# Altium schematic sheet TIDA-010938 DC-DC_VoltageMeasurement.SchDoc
size 431 x 279 mm; Date: Not shown in title block; ApprovedBy: Not shown in title block; CheckedBy: Not shown in title block; Author: Not shown in title block; CompanyName: Not shown in title block; Engineer: Not shown in title block; Organization: Not shown in title block; Address1: Not shown in title block; Address2: Not shown in title block; Address3: Not shown in title block; Address4: Not shown in title block; DocumentNumber: 1; Revision: Use project parameter SCH_Rev; SheetNumber: 8; SheetTotal: 9; PageSetup: Record=PageOptions¦CenterHorizontal=True¦CenterVertical=True¦PrintScale=1.00¦XCorrection=1.00¦YCorrection=1.00¦PrintKind=0¦BorderSize=5000000¦LeftOffset=0¦BottomOffset=0¦Orientation=2¦PaperLength=1000¦PaperWidth=1000¦Scale=100¦PaperSource=15¦PrintQuality=600¦MediaType=1¦DitherType=10¦PaperKind=Letter¦PrintScaleMode=1
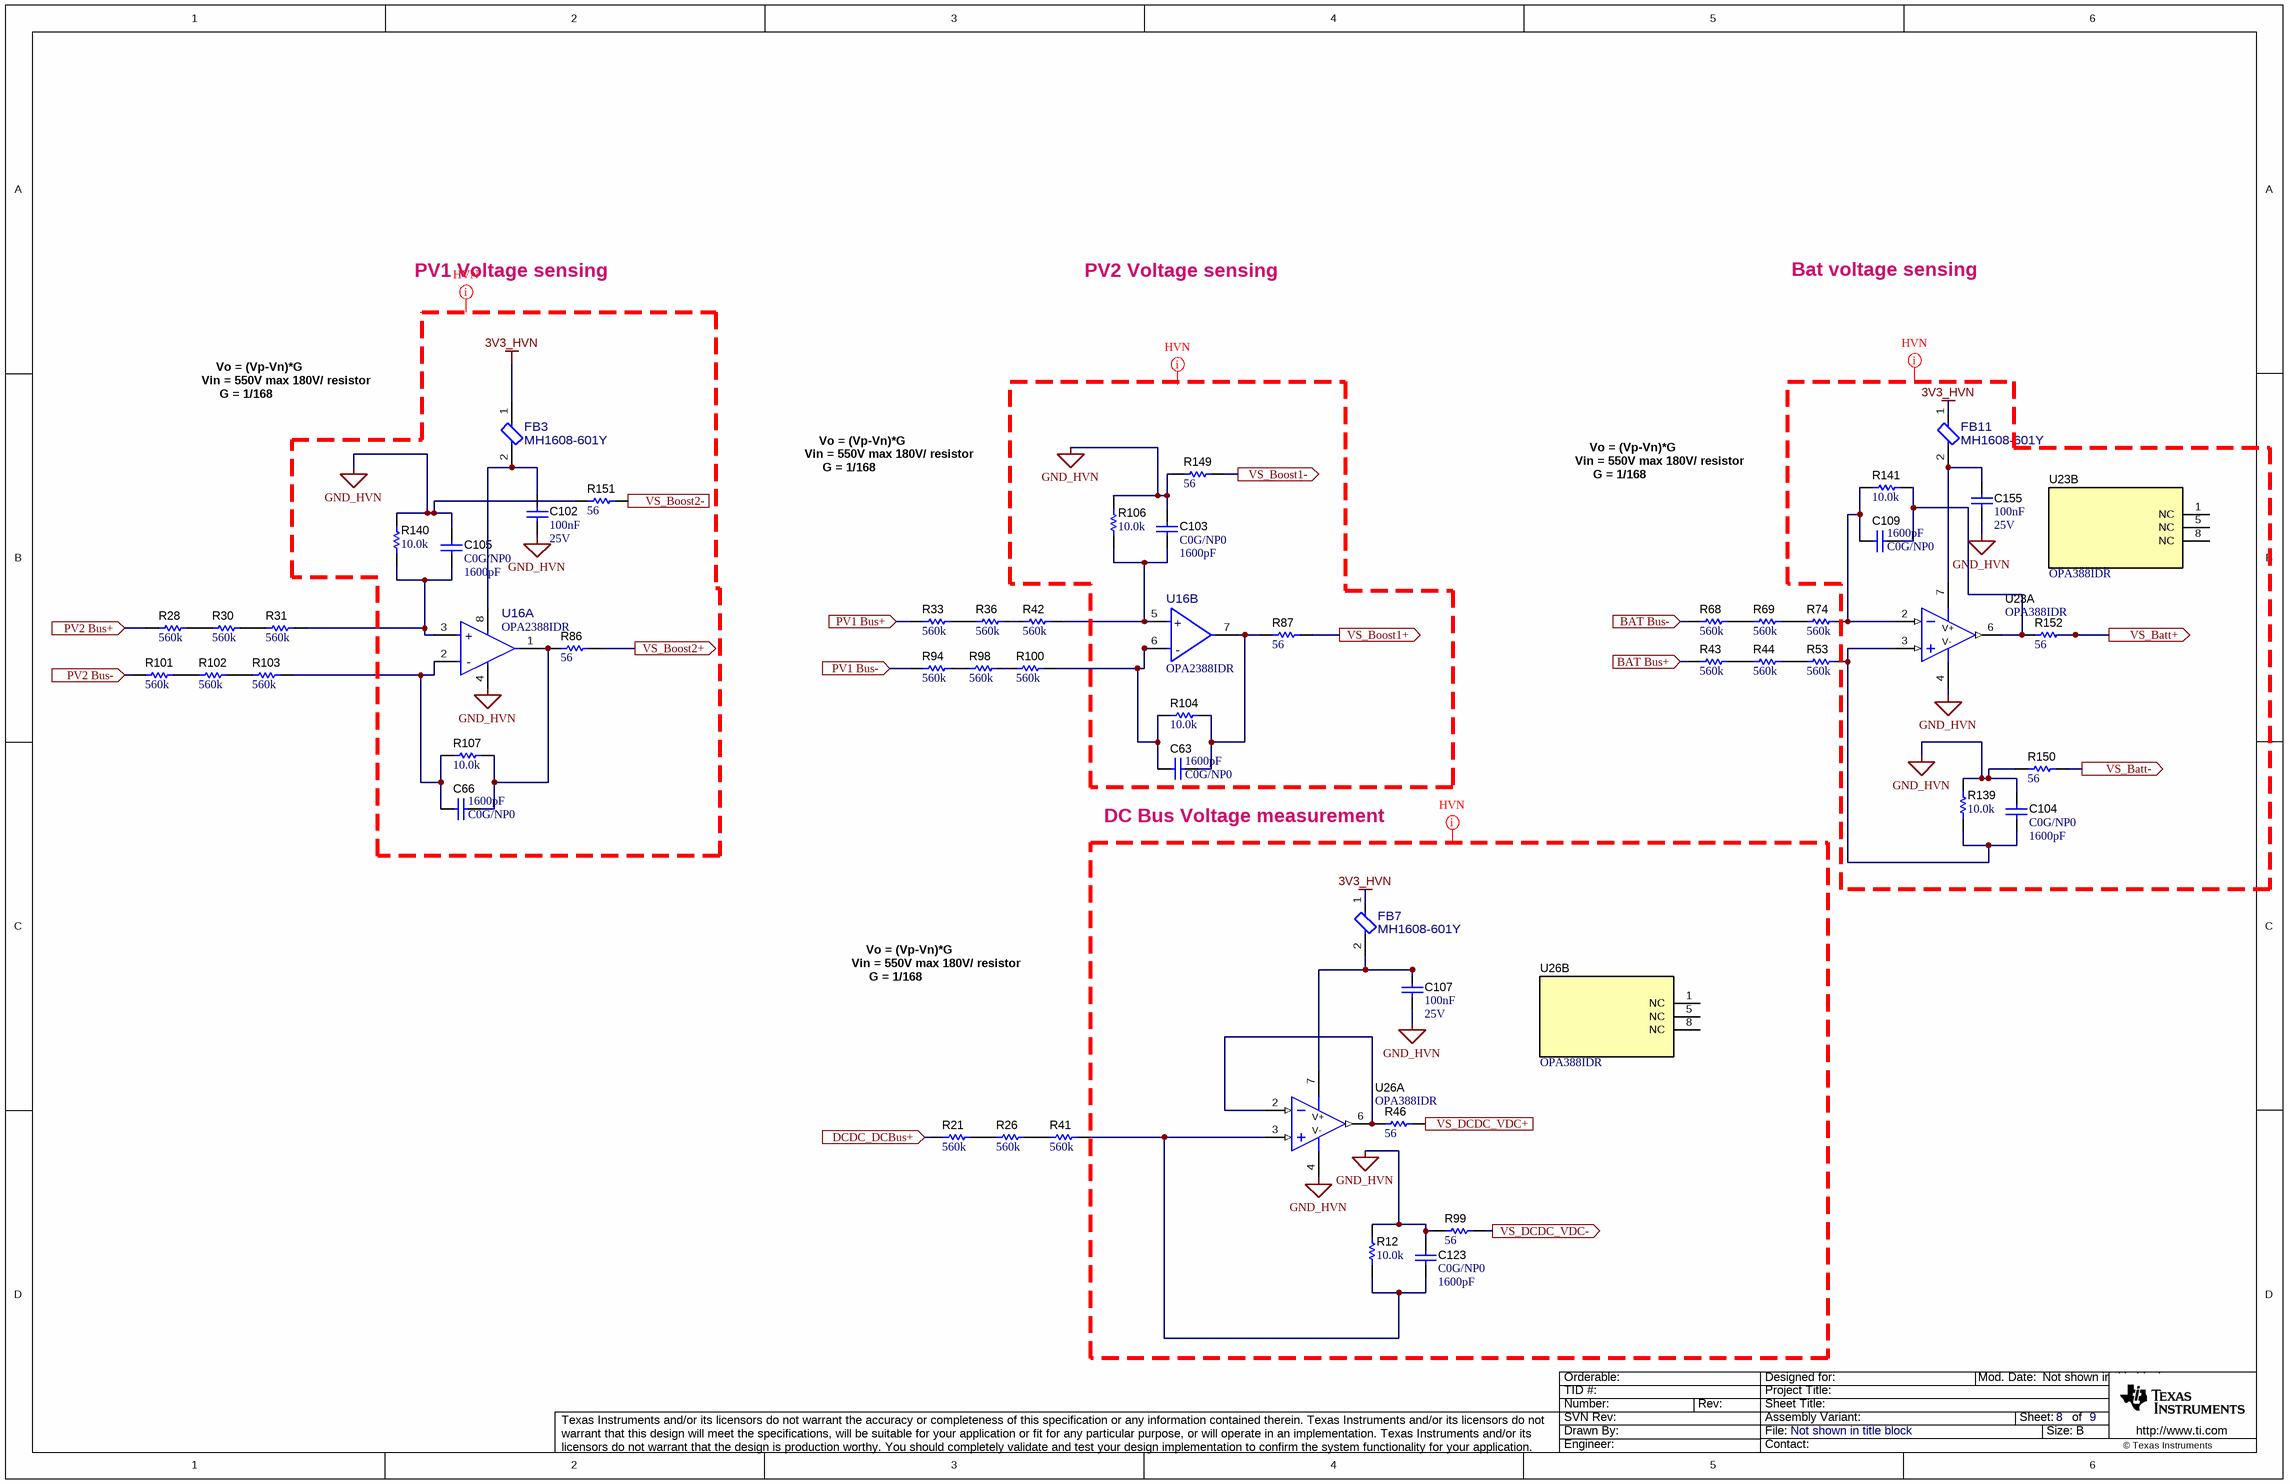
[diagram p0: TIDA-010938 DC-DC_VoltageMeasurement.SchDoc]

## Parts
C63  TempCo: C0G/NP0  ValueDisplayed: 1600pF  [0603]  (hidden comment: GRM1885C1H162JA01D)
C66  TempCo: C0G/NP0  ValueDisplayed: 1600pF  [0603]  (hidden comment: GRM1885C1H162JA01D)
C102  Cap_F: 100nF  VDC_V: 25V  [0603]  (hidden comment: 06033C104JAT2A)
C103  TempCo: C0G/NP0  ValueDisplayed: 1600pF  [0603]  (hidden comment: GRM1885C1H162JA01D)
C104  TempCo: C0G/NP0  ValueDisplayed: 1600pF  [0603]  (hidden comment: GRM1885C1H162JA01D)
C105  TempCo: C0G/NP0  ValueDisplayed: 1600pF  [0603]  (hidden comment: GRM1885C1H162JA01D)
C107  Cap_F: 100nF  VDC_V: 25V  [0603]  (hidden comment: 06033C104JAT2A)
C109  TempCo: C0G/NP0  ValueDisplayed: 1600pF  [0603]  (hidden comment: GRM1885C1H162JA01D)
C123  TempCo: C0G/NP0  ValueDisplayed: 1600pF  [0603]  (hidden comment: GRM1885C1H162JA01D)
C155  Cap_F: 100nF  VDC_V: 25V  [0603]  (hidden comment: 06033C104JAT2A)
FB3  MH1608-601Y  [FP-MH1608-601Y_0603-MFG]
FB7  MH1608-601Y  [FP-MH1608-601Y_0603-MFG]
FB11  MH1608-601Y  [FP-MH1608-601Y_0603-MFG]
R12  ValueDisplayed: 10.0k  [0603]  (hidden comment: RG1608P-103-B-T5)
R21  ValueDisplayed: 560k  [TNPV1206]  (hidden comment: TNPV1206560KBEEN)
R26  ValueDisplayed: 560k  [TNPV1206]  (hidden comment: TNPV1206560KBEEN)
R28  ValueDisplayed: 560k  [TNPV1206]  (hidden comment: TNPV1206560KBEEN)
R30  ValueDisplayed: 560k  [TNPV1206]  (hidden comment: TNPV1206560KBEEN)
R31  ValueDisplayed: 560k  [TNPV1206]  (hidden comment: TNPV1206560KBEEN)
R33  ValueDisplayed: 560k  [TNPV1206]  (hidden comment: TNPV1206560KBEEN)
R36  ValueDisplayed: 560k  [TNPV1206]  (hidden comment: TNPV1206560KBEEN)
R41  ValueDisplayed: 560k  [TNPV1206]  (hidden comment: TNPV1206560KBEEN)
R42  ValueDisplayed: 560k  [TNPV1206]  (hidden comment: TNPV1206560KBEEN)
R43  ValueDisplayed: 560k  [TNPV1206]  (hidden comment: TNPV1206560KBEEN)
R44  ValueDisplayed: 560k  [TNPV1206]  (hidden comment: TNPV1206560KBEEN)
R46  ValueDisplayed: 56  [0603]  (hidden comment: RG1608P-560-B-T5)
R53  ValueDisplayed: 560k  [TNPV1206]  (hidden comment: TNPV1206560KBEEN)
R68  ValueDisplayed: 560k  [TNPV1206]  (hidden comment: TNPV1206560KBEEN)
R69  ValueDisplayed: 560k  [TNPV1206]  (hidden comment: TNPV1206560KBEEN)
R74  ValueDisplayed: 560k  [TNPV1206]  (hidden comment: TNPV1206560KBEEN)
R86  ValueDisplayed: 56  [0603]  (hidden comment: RG1608P-560-B-T5)
R87  ValueDisplayed: 56  [0603]  (hidden comment: RG1608P-560-B-T5)
R94  ValueDisplayed: 560k  [TNPV1206]  (hidden comment: TNPV1206560KBEEN)
R98  ValueDisplayed: 560k  [TNPV1206]  (hidden comment: TNPV1206560KBEEN)
R99  ValueDisplayed: 56  [0603]  (hidden comment: RG1608P-560-B-T5)
R100  ValueDisplayed: 560k  [TNPV1206]  (hidden comment: TNPV1206560KBEEN)
R101  ValueDisplayed: 560k  [TNPV1206]  (hidden comment: TNPV1206560KBEEN)
R102  ValueDisplayed: 560k  [TNPV1206]  (hidden comment: TNPV1206560KBEEN)
R103  ValueDisplayed: 560k  [TNPV1206]  (hidden comment: TNPV1206560KBEEN)
R104  ValueDisplayed: 10.0k  [0603]  (hidden comment: RG1608P-103-B-T5)
R106  ValueDisplayed: 10.0k  [0603]  (hidden comment: RG1608P-103-B-T5)
R107  ValueDisplayed: 10.0k  [0603]  (hidden comment: RG1608P-103-B-T5)
R139  ValueDisplayed: 10.0k  [0603]  (hidden comment: RG1608P-103-B-T5)
R140  ValueDisplayed: 10.0k  [0603]  (hidden comment: RG1608P-103-B-T5)
R141  ValueDisplayed: 10.0k  [0603]  (hidden comment: RG1608P-103-B-T5)
R149  ValueDisplayed: 56  [0603]  (hidden comment: RG1608P-560-B-T5)
R150  ValueDisplayed: 56  [0603]  (hidden comment: RG1608P-560-B-T5)
R151  ValueDisplayed: 56  [0603]  (hidden comment: RG1608P-560-B-T5)
R152  ValueDisplayed: 56  [0603]  (hidden comment: RG1608P-560-B-T5)
U16  OPA2388IDR  [D0008A-MFG]  (parts A,B of 2)
U23  OPA388IDR  [D0008A_L]  (parts A,B of 2)
U26  OPA388IDR  [D0008A_L]  (parts A,B of 2)

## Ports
BAT Bus+ (in), BAT Bus- (in), DCDC_DCBus+ (in), PV1 Bus+ (in), PV1 Bus- (in), PV2 Bus+ (in), PV2 Bus- (in), VS_Batt+ (out), VS_Batt- (out), VS_Boost1+ (out), VS_Boost1- (out), VS_Boost2+ (out), VS_Boost2- (out), VS_DCDC_VDC+ (out), VS_DCDC_VDC- (out)

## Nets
3V3_HVN: FB3.1 FB7.1 FB11.1
GND_HVN: C102.1 C103.1 C104.1 C105.1 C107.1 C123.1 C155.1 R12.2 R99.1 R106.2 R139.2 R140.1 R149.1 R150.1 R151.1 U16.4(V-) U23.4(V-) U26.4(V-)
BAT Bus+: R43.1 ; port BAT Bus+
BAT Bus-: R68.1 ; port BAT Bus-
DCDC_DCBus+: R21.1 ; port DCDC_DCBus+
PV1 Bus+: R33.1 ; port PV1 Bus+
PV1 Bus-: R94.1 ; port PV1 Bus-
PV2 Bus+: R28.1 ; port PV2 Bus+
PV2 Bus-: R101.1 ; port PV2 Bus-
VS_Batt+: R152.2 ; port VS_Batt+
VS_Batt-: R150.2 ; port VS_Batt-
VS_Boost1+: R87.2 ; port VS_Boost1+
VS_Boost1-: R149.2 ; port VS_Boost1-
VS_Boost2+: R86.2 ; port VS_Boost2+
VS_Boost2-: R151.2 ; port VS_Boost2-
VS_DCDC_VDC+: R46.2 ; port VS_DCDC_VDC+
VS_DCDC_VDC-: R99.2 ; port VS_DCDC_VDC-
NetC63_1: C63.1 R100.2 R104.1 U16.6(-IN_B)
NetC63_2: C63.2 R87.1 R104.2 U16.7(OUT_B)
NetC66_1: C66.1 R103.2 R107.1 U16.2(-IN_A)
NetC66_2: C66.2 R86.1 R107.2 U16.1(OUT_A)
NetC102_2: C102.2 FB3.2 U16.8(V+)
NetC103_2: C103.2 R42.2 R106.1 U16.5(+IN_B)
NetC104_2: C104.2 R53.2 R139.1 U23.3(IN+)
NetC105_2: C105.2 R31.2 R140.2 U16.3(+IN_A)
NetC107_2: C107.2 FB7.2 U26.7(V+)
NetC109_1: C109.1 R74.2 R141.1 U23.2(IN-)
NetC109_2: C109.2 R141.2 R152.1 U23.6(OUT)
NetC123_2: C123.2 R12.1 R41.2 U26.3(IN+)
NetC155_2: C155.2 FB11.2 U23.7(V+)
NetR21_2: R21.2 R26.1
NetR26_2: R26.2 R41.1
NetR28_2: R28.2 R30.1
NetR30_2: R30.2 R31.1
NetR33_2: R33.2 R36.1
NetR36_2: R36.2 R42.1
NetR43_2: R43.2 R44.1
NetR44_2: R44.2 R53.1
NetR46_1: R46.1 U26.2(IN-) U26.6(OUT)
NetR68_2: R68.2 R69.1
NetR69_2: R69.2 R74.1
NetR94_2: R94.2 R98.1
NetR98_2: R98.2 R100.1
NetR101_2: R101.2 R102.1
NetR102_2: R102.2 R103.1

Not connected (* = marked no-connect by the designer): U23 1(NC) 5(NC) 8(NC); U26 1(NC) 5(NC) 8(NC)

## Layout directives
net class HVN: 3V3_HVN, GND_HVN

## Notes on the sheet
- PV1 Voltage sensing
- PV2 Voltage sensing
- Bat voltage sensing
- Vo = (Vp-Vn)*G
- G = 1/168
- Vin = 550V max 180V/ resistor
- (near C63) DC Bus Voltage measurement

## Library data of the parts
C63 C66 C103-C105 C109 C123 = CMP-0007189-4: CAP, CERM, 1600 pF, 50 V, +/- 5%, C0G/NP0, 0603; Manufacturer: MuRata; TaMin_C: -55°C; Polarized: N; SizeAreaWB_mm2: 4.68; Value1: Unknown; U/M: EA; Value: 1600pF; TaMax_C: 125°C; SizeZ_mm: 1; SizeX_mm: 1.6; SizeY_mm: 0.8; Value2: 50V; SizeArea_mm2: 1.28; Cap_F: 1.6nF; AEC Category: Q200
C102 C107 C155 = CMP-0006752-5: CAP, CERM, 0.1 uF, 25 V, +/- 5%, X7R, 0603; Manufacturer: AVX; TaMin_C: -55°C; ESR_ohm: 0.05; Polarized: N; SizeAreaWB_mm2: 4.68; Value1: 0.05 ohm; U/M: EA; Value: 0.1uF; TaMax_C: 125°C; SizeZ_mm: 1; SizeX_mm: 1.6; SizeY_mm: 0.8; SizeArea_mm2: 1.28; AEC Category: Q200
FB3 FB7 FB11 = CMP-0037505-1: 600 Ohms @ 100 MHz 1 Power, Signal Line Ferrite Bead 0603 (1608 Metric) 1A 200mOhm; Manufacturer: Bourns; DCR_ohm: 0.2; SizeZ_mm: 1mm; AEC Qualified: No; Impedance At Frequency: 600Ω @ 100MHz; Test Frequency: 100MHz; Tolerance_%: 25%
R12 R104 R106 R107 R139-R141 = CMP-0023404-3: RES, 10.0 k, 0.1%, 0.1 W, 0603; Manufacturer: Susumu Co Ltd; Power_W: 100mW; TempCo: 25 ppm/C; Value_Code: 10k0; U/M: EA; Value: 10.0k; EIA_Code: E192; Res_ohm: 10k; SizeX_mm: 1.6; SizeY_mm: 0.8; SizeZ_mm: 1; Value2: 0.1W; SizeArea_mm2: 1.28; VDC_V: 75V; AEC Category: Q200
R21 R26 R28 R30 R31 R33 R36 R41-R44 R53 R68 R69 R74 R94 R98 R100-R103 = CMP-0018815-2: RES, 560 k, 0.1%, 1 W, 1206; Manufacturer: Vishay Draloric; Power_W: 1W; TempCo: 25 ppm/C; U/M: EA; Value: 560k; SizeX_mm: 3.2; SizeY_mm: 1.6; SizeZ_mm: 0.65; SizeArea_mm2: 5.12; AEC Qualified: N; VDC_V: 700V; AEC Category: Q200
R46 R86 R87 R99 R149-R152 = CMP-0023572-3: RES, 56, 0.1%, 0.1 W, 0603; Manufacturer: Susumu Co Ltd; Power_W: 100mW; TempCo: 25 ppm/C; Value_Code: 56R0; U/M: EA; Value: 56; SizeX_mm: 1.6; SizeY_mm: 0.8; SizeZ_mm: 1; Value2: 0.1W; SizeArea_mm2: 1.28; VDC_V: 75V; AEC Category: Q200
U16 = CMP-0097119-1: Precision, Zero-Drift, Zero-Crossover, True Rail-to-Rail, Input/Output Operational Amplifiers; Manufacturer: Texas Instruments; TJmax_C: +150°C; TaMin_C: -55°C; AEC Qualified: No; Max Dual Supply Voltage: 2.75V; Min Dual Supply Voltage: 1.25V; Input Offset Voltage: 0.00025mV; Output Current Per Channel: 30-60mA; Standoff Height: 0.11mm; Number Of Channels: 2; Min Supply Voltage: 2.5V; Input Bias Current: 0.00003uA; Nominal Supply Current: 1.7-1.9mA; Voltage Gain: 126-148dB; Bandwidth: 10MHz; SizeZ_mm: 1.75mm; Max Supply Voltage: 5.5V; Response Time: 0.75-2us
U23 U26 = CMP-0075798-1: Precision, Zero-Drift, Zero-Crossover, True Rail-to-Rail Input/Output, Operational Amplifier, D0008A (SOIC-8); Manufacturer: Texas Instruments; SizeAreaWB_mm2: 56.58; SizeArea_mm2: 30.38; SizeZ_mm: 1.75; SizeY_mm: 6.2; U/M: EA; CompType: IC; SizeX_mm: 4.9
